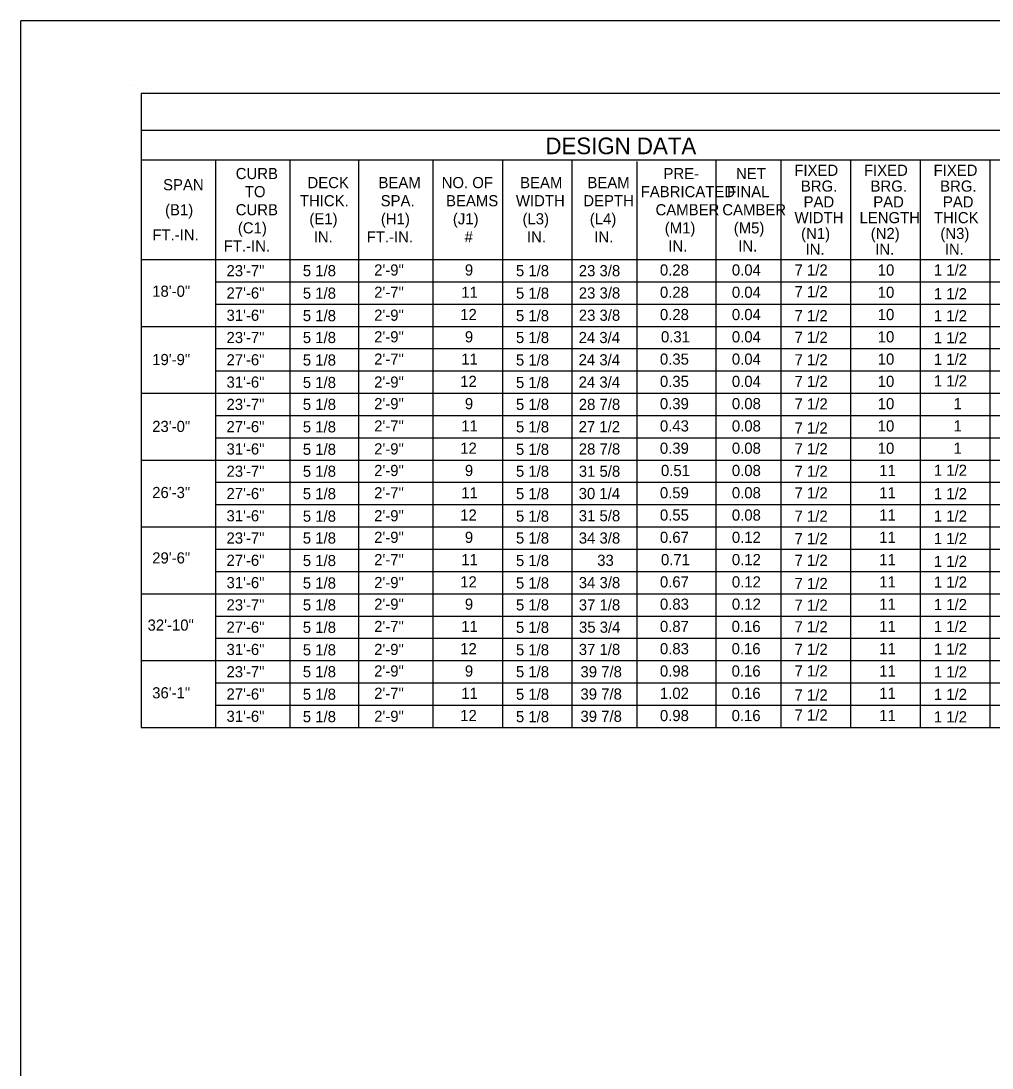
# Model space of a CAD drawing. Extents: x -5022 to -159, y 1126 to 7226.
# Drawn here: x -3800.1 to -3538.7, y 5580.8 to 5862.8 of the extents above; entities that cross this region are included whole.
import ezdxf

# ---------------------------------------------------------------- set-up
doc = ezdxf.new("R2010")
doc.units = 0
doc.layers.add('2', color=7, linetype='Continuous')
doc.layers.add('3', color=7, linetype='Continuous')

msp = doc.modelspace()

# ---------------------------------------------------------------- linework, layer by layer
at = {"layer": '2'}
for p, q in [((-3014.13, 5862.81), (-3800.13, 5862.81)), ((-3800.13, 5298.81), (-3800.13, 5862.81)), ((-3769.75, 5845.32), (-3769.75, 5845.32)), ((-3766.35, 5844.74), (-3766.35, 5844.74)), ((-3766.35, 5844.74), (-3766.35, 5844.74))]:
    msp.add_line(p, q, dxfattribs=at)
at = {"layer": '3'}
for p, q in [((-3767.78, 5843.35), (-3767.78, 5672.54)), ((-3767.78, 5843.35), (-3053.03, 5843.35)), ((-3767.78, 5833.43), (-3053.03, 5833.43)), ((-3767.78, 5825.36), (-3053.03, 5825.36)), ((-3747.78, 5825.36), (-3747.78, 5672.54)), ((-3727.78, 5825.36), (-3727.78, 5672.54)), ((-3709.28, 5825.36), (-3709.28, 5672.54)), ((-3689.28, 5825.36), (-3689.28, 5672.54)), ((-3670.53, 5825.36), (-3670.53, 5672.54)), ((-3651.78, 5825.36), (-3651.78, 5672.54)), ((-3634.28, 5824.97), (-3634.28, 5672.54)), ((-3613.03, 5825.36), (-3613.03, 5672.54)), ((-3595.53, 5825.36), (-3595.53, 5672.54)), ((-3576.78, 5825.36), (-3576.78, 5672.54)), ((-3558.03, 5825.36), (-3558.03, 5672.54)), ((-3539.28, 5825.36), (-3539.28, 5672.54)), ((-3767.78, 5798.55), (-3053.03, 5798.55)), ((-3747.78, 5792.55), (-3053.03, 5792.55)), ((-3747.78, 5786.55), (-3053.03, 5786.55)), ((-3767.78, 5780.55), (-3053.03, 5780.55)), ((-3747.78, 5774.55), (-3053.03, 5774.55)), ((-3747.78, 5768.54), (-3053.03, 5768.55)), ((-3767.78, 5762.55), (-3053.03, 5762.55)), ((-3747.78, 5756.55), (-3053.03, 5756.55)), ((-3747.78, 5750.55), (-3053.03, 5750.55)), ((-3767.78, 5744.55), (-3053.03, 5744.55)), ((-3747.78, 5738.55), (-3053.03, 5738.55)), ((-3747.78, 5732.55), (-3053.03, 5732.55)), ((-3767.78, 5726.55), (-3053.03, 5726.55)), ((-3747.78, 5720.55), (-3053.03, 5720.55)), ((-3747.78, 5714.55), (-3053.03, 5714.55)), ((-3767.78, 5708.54), (-3053.03, 5708.55)), ((-3747.78, 5702.54), (-3053.03, 5702.55)), ((-3747.78, 5696.54), (-3053.03, 5696.55)), ((-3767.78, 5690.54), (-3053.03, 5690.54)), ((-3747.78, 5684.54), (-3053.03, 5684.55)), ((-3747.78, 5678.54), (-3053.03, 5678.55)), ((-3767.78, 5672.54), (-3053.03, 5672.55))]:
    msp.add_line(p, q, dxfattribs=at)

# ---------------------------------------------------------------- texts
at = {"layer": '2'}
for s, height, p in [('DESIGN DATA', 4.4793, (-3658.93, 5826.92)), ('FIXED', 3, (-3591.93, 5821.08)), ('FIXED', 3, (-3573.18, 5821.08)), ('FIXED', 3, (-3554.43, 5821.08)), ('CURB', 3, (-3742.31, 5820.21)), ('DECK', 3, (-3722.99, 5817.77)), ('BEAM', 3, (-3703.87, 5817.77)), ('NO. OF', 3, (-3686.87, 5817.77)), ('BEAM', 3, (-3665.74, 5817.77)), ('BEAM', 3, (-3647.62, 5817.77)), ('PRE-', 3, (-3627.14, 5820.21)), ('NET', 3, (-3607.61, 5820.21)), ('SPAN', 3, (-3761.86, 5817.2)), ('TO', 3, (-3739.85, 5815.33)), ('FABRICATED', 3, (-3633.28, 5815.33)), ('FINAL', 3, (-3609.99, 5815.33)), ('BRG.', 3, (-3590.16, 5816.83)), ('BRG.', 3, (-3571.41, 5816.83)), ('BRG.', 3, (-3552.66, 5816.83)), ('THICK.', 3, (-3725.04, 5812.89)), ('SPA.', 3, (-3703.29, 5812.89)), ('BEAMS', 3, (-3685.68, 5812.89)), ('WIDTH', 3, (-3666.87, 5812.89)), ('DEPTH', 3, (-3648.74, 5812.89)), ('PAD', 3, (-3589.43, 5812.58)), ('PAD', 3, (-3570.68, 5812.58)), ('PAD', 3, (-3551.93, 5812.58)), ('(B1)', 3, (-3761.33, 5810.46)), ('CURB', 3, (-3742.31, 5810.46)), ('CAMBER', 3, (-3629.28, 5810.46)), ('CAMBER', 3, (-3611.31, 5810.46)), ('(E1)', 3, (-3722.48, 5808.02)), ('(H1)', 3, (-3703.23, 5808.02)), ('(J1)', 3, (-3683.85, 5808.02)), ('(L3)', 3, (-3665.1, 5808.02)), ('(L4)', 3, (-3646.98, 5808.02)), ('WIDTH', 3, (-3591.86, 5808.33)), ('LENGTH', 3, (-3574.36, 5808.33)), ('THICK', 3, (-3554.36, 5808.33)), ('FT.-IN.', 3, (-3764.76, 5803.7)), ('(C1)', 3, (-3741.73, 5805.58)), ('(M1)', 3, (-3626.81, 5805.58)), ('(M5)', 3, (-3608.23, 5805.58)), ('(N1)', 3, (-3590.1, 5804.08)), ('(N2)', 3, (-3571.35, 5804.08)), ('(N3)', 3, (-3552.6, 5804.08)), ('FT.-IN.', 3, (-3745.53, 5800.71)), ('IN.', 3, (-3721.29, 5803.14)), ('FT.-IN.', 3, (-3707.04, 5803.14)), ('#', 3, (-3680.7, 5803.14)), ('IN.', 3, (-3663.91, 5803.14)), ('IN.', 3, (-3645.79, 5803.14)), ('IN.', 3, (-3625.86, 5800.71)), ('IN.', 3, (-3607.03, 5800.71)), ('IN.', 3, (-3588.91, 5799.83)), ('IN.', 3, (-3570.16, 5799.83)), ('IN.', 3, (-3551.41, 5799.83)), ('23\'-7"', 3, (-3744.79, 5794.05)), ('5 1/8', 3, (-3724.24, 5794.05)), ('2\'-9"', 3, (-3705.04, 5794.24)), ('9', 3, (-3680.62, 5794.24)), ('5 1/8', 3, (-3666.87, 5794.05)), ('23 3/8', 3, (-3649.95, 5794.05)), ('0.28', 3, (-3628.11, 5794.24)), ('0.04', 3, (-3608.74, 5794.24)), ('7 1/2', 3, (-3591.86, 5794.24)), ('10', 3, (-3569.47, 5794.24)), ('1 1/2', 3, (-3554.36, 5794.24)), ('18\'-0"', 3, (-3764.79, 5788.52)), ('27\'-6"', 3, (-3744.79, 5788.05)), ('5 1/8', 3, (-3724.24, 5787.99)), ('2\'-7"', 3, (-3705.04, 5788.24)), ('11', 3, (-3681.58, 5788.24)), ('5 1/8', 3, (-3666.87, 5787.99)), ('23 3/8', 3, (-3649.95, 5788.05)), ('0.28', 3, (-3628.11, 5788.24)), ('0.04', 3, (-3608.74, 5788.24)), ('7 1/2', 3, (-3591.86, 5788.41)), ('10', 3, (-3569.47, 5788.24)), ('1 1/2', 3, (-3554.36, 5787.84)), ('31\'-6"', 3, (-3744.79, 5782.04)), ('5 1/8', 3, (-3724.24, 5781.94)), ('2\'-9"', 3, (-3705.04, 5782.06)), ('12', 3, (-3681.87, 5782.24)), ('5 1/8', 3, (-3666.87, 5781.94)), ('23 3/8', 3, (-3649.95, 5782.05)), ('0.28', 3, (-3628.11, 5782.24)), ('0.04', 3, (-3608.74, 5782.24)), ('7 1/2', 3, (-3591.86, 5781.93)), ('10', 3, (-3569.47, 5782.24)), ('1 1/2', 3, (-3554.36, 5781.91)), ('23\'-7"', 3, (-3744.79, 5776.05)), ('5 1/8', 3, (-3724.24, 5776.05)), ('2\'-9"', 3, (-3705.04, 5776.24)), ('9', 3, (-3680.62, 5776.24)), ('5 1/8', 3, (-3666.87, 5776.05)), ('24 3/4', 3, (-3649.99, 5776.05)), ('0.31', 3, (-3627.83, 5776.24)), ('0.04', 3, (-3608.74, 5776.24)), ('7 1/2', 3, (-3591.86, 5776.1)), ('10', 3, (-3569.47, 5776.24)), ('1 1/2', 3, (-3554.36, 5775.98)), ('19\'-9"', 3, (-3764.79, 5770.12)), ('27\'-6"', 3, (-3744.79, 5770.05)), ('5 1/8', 3, (-3724.24, 5769.99)), ('2\'-7"', 3, (-3705.04, 5770.24)), ('11', 3, (-3681.58, 5770.24)), ('5 1/8', 3, (-3666.87, 5769.99)), ('24 3/4', 3, (-3649.99, 5770.05)), ('0.35', 3, (-3628.11, 5770.24)), ('0.04', 3, (-3608.74, 5770.24)), ('7 1/2', 3, (-3591.86, 5770.05)), ('10', 3, (-3569.47, 5770.24)), ('1 1/2', 3, (-3554.36, 5770.18)), ('31\'-6"', 3, (-3744.79, 5764.04)), ('5 1/8', 3, (-3724.24, 5763.94)), ('2\'-9"', 3, (-3705.04, 5764.06)), ('12', 3, (-3681.87, 5764.24)), ('5 1/8', 3, (-3666.87, 5763.94)), ('24 3/4', 3, (-3649.99, 5764.04)), ('0.35', 3, (-3628.11, 5764.24)), ('0.04', 3, (-3608.74, 5764.24)), ('7 1/2', 3, (-3591.86, 5764.22)), ('10', 3, (-3569.47, 5764.24)), ('1 1/2', 3, (-3554.36, 5764.37)), ('2\'-9"', 3, (-3705.04, 5758.24)), ('9', 3, (-3680.62, 5758.24)), ('0.39', 3, (-3628.12, 5758.24)), ('0.08', 3, (-3608.74, 5758.24)), ('7 1/2', 3, (-3591.86, 5758.17)), ('10', 3, (-3569.47, 5758.24)), ('23\'-7"', 3, (-3744.79, 5758.04)), ('5 1/8', 3, (-3724.24, 5758.04)), ('5 1/8', 3, (-3666.87, 5758.04)), ('28 7/8', 3, (-3649.95, 5758.04)), ('1', 3, (-3549.08, 5758.24)), ('23\'-0"', 3, (-3764.79, 5752.11)), ('27\'-6"', 3, (-3744.79, 5752.05)), ('5 1/8', 3, (-3724.24, 5751.99)), ('2\'-7"', 3, (-3705.04, 5752.24)), ('11', 3, (-3681.58, 5752.24)), ('5 1/8', 3, (-3666.87, 5751.99)), ('27 1/2', 3, (-3649.99, 5752.04)), ('0.43', 3, (-3628.11, 5752.24)), ('0.08', 3, (-3608.74, 5752.24)), ('7 1/2', 3, (-3591.86, 5751.69)), ('10', 3, (-3569.47, 5752.24)), ('1', 3, (-3549.08, 5752.24)), ('31\'-6"', 3, (-3744.79, 5746.04)), ('5 1/8', 3, (-3724.24, 5745.94)), ('2\'-9"', 3, (-3705.04, 5746.06)), ('12', 3, (-3681.87, 5746.24)), ('5 1/8', 3, (-3666.87, 5745.94)), ('28 7/8', 3, (-3649.95, 5746.04)), ('0.39', 3, (-3628.12, 5746.24)), ('0.08', 3, (-3608.74, 5746.24)), ('7 1/2', 3, (-3591.86, 5746.08)), ('10', 3, (-3569.47, 5746.24)), ('1', 3, (-3549.08, 5746.24)), ('23\'-7"', 3, (-3744.79, 5740.04)), ('5 1/8', 3, (-3724.24, 5740.04)), ('2\'-9"', 3, (-3705.04, 5740.24)), ('9', 3, (-3680.62, 5740.24)), ('5 1/8', 3, (-3666.87, 5740.04)), ('31 5/8', 3, (-3649.95, 5740.04)), ('0.51', 3, (-3627.83, 5740.24)), ('0.08', 3, (-3608.74, 5740.24)), ('7 1/2', 3, (-3591.86, 5740.03)), ('11', 3, (-3569.08, 5740.24)), ('1 1/2', 3, (-3554.36, 5740.3)), ('26\'-3"', 3, (-3764.79, 5734.31)), ('27\'-6"', 3, (-3744.79, 5734.04)), ('5 1/8', 3, (-3724.24, 5733.99)), ('2\'-7"', 3, (-3705.04, 5734.24)), ('11', 3, (-3681.58, 5734.24)), ('5 1/8', 3, (-3666.87, 5733.99)), ('30 1/4', 3, (-3649.99, 5734.04)), ('0.59', 3, (-3628.12, 5734.24)), ('0.08', 3, (-3608.74, 5734.24)), ('7 1/2', 3, (-3591.86, 5734.2)), ('11', 3, (-3569.08, 5734.24)), ('1 1/2', 3, (-3554.36, 5734.01)), ('31\'-6"', 3, (-3744.79, 5728.04)), ('5 1/8', 3, (-3724.24, 5727.94)), ('2\'-9"', 3, (-3705.04, 5728.06)), ('12', 3, (-3681.87, 5728.24)), ('5 1/8', 3, (-3666.87, 5727.94)), ('31 5/8', 3, (-3649.95, 5728.05)), ('0.55', 3, (-3628.11, 5728.24)), ('0.08', 3, (-3608.74, 5728.24)), ('7 1/2', 3, (-3591.86, 5727.94)), ('11', 3, (-3569.08, 5728.24)), ('1 1/2', 3, (-3554.36, 5727.96)), ('23\'-7"', 3, (-3744.79, 5722.05)), ('5 1/8', 3, (-3724.24, 5722.05)), ('2\'-9"', 3, (-3705.04, 5722.24)), ('9', 3, (-3680.62, 5722.24)), ('5 1/8', 3, (-3666.87, 5722.05)), ('34 3/8', 3, (-3649.95, 5722.05)), ('0.67', 3, (-3628.11, 5722.24)), ('0.12', 3, (-3608.74, 5722.24)), ('7 1/2', 3, (-3591.86, 5721.89)), ('11', 3, (-3569.08, 5722.24)), ('1 1/2', 3, (-3554.36, 5721.92)), ('29\'-6"', 3, (-3764.79, 5716.7)), ('27\'-6"', 3, (-3744.79, 5716.05)), ('5 1/8', 3, (-3724.24, 5715.99)), ('2\'-7"', 3, (-3705.04, 5716.24)), ('11', 3, (-3681.58, 5716.24)), ('5 1/8', 3, (-3666.87, 5715.99)), ('33', 3, (-3644.99, 5716.05)), ('0.71', 3, (-3627.83, 5716.24)), ('0.12', 3, (-3608.74, 5716.24)), ('7 1/2', 3, (-3591.86, 5716.06)), ('11', 3, (-3569.08, 5716.24)), ('1 1/2', 3, (-3554.36, 5715.75)), ('1 1/2', 3, (-3554.36, 5710.18)), ('31\'-6"', 3, (-3744.79, 5710.04)), ('5 1/8', 3, (-3724.24, 5709.94)), ('2\'-9"', 3, (-3705.04, 5710.06)), ('12', 3, (-3681.87, 5710.24)), ('5 1/8', 3, (-3666.87, 5709.94)), ('34 3/8', 3, (-3649.95, 5710.04)), ('0.67', 3, (-3628.11, 5710.24)), ('0.12', 3, (-3608.74, 5710.24)), ('7 1/2', 3, (-3591.86, 5709.8)), ('11', 3, (-3569.08, 5710.24)), ('23\'-7"', 3, (-3744.79, 5704.04)), ('5 1/8', 3, (-3724.24, 5704.04)), ('2\'-9"', 3, (-3705.04, 5704.24)), ('9', 3, (-3680.62, 5704.24)), ('5 1/8', 3, (-3666.87, 5704.04)), ('37 1/8', 3, (-3649.95, 5704.04)), ('0.83', 3, (-3628.11, 5704.24)), ('0.12', 3, (-3608.74, 5704.24)), ('7 1/2', 3, (-3591.86, 5703.97)), ('11', 3, (-3569.08, 5704.24)), ('1 1/2', 3, (-3554.36, 5704.13)), ('32\'-10"', 3, (-3766.04, 5698.61)), ('27\'-6"', 3, (-3744.79, 5698.04)), ('5 1/8', 3, (-3724.24, 5697.99)), ('2\'-7"', 3, (-3705.04, 5698.24)), ('11', 3, (-3681.58, 5698.24)), ('5 1/8', 3, (-3666.87, 5697.99)), ('35 3/4', 3, (-3649.9, 5698.04)), ('0.87', 3, (-3628.11, 5698.24)), ('0.16', 3, (-3608.81, 5698.24)), ('7 1/2', 3, (-3591.86, 5698.14)), ('11', 3, (-3569.08, 5698.24)), ('1 1/2', 3, (-3554.36, 5698.2)), ('31\'-6"', 3, (-3744.79, 5692.04)), ('5 1/8', 3, (-3724.24, 5691.94)), ('2\'-9"', 3, (-3705.04, 5692.05)), ('12', 3, (-3681.87, 5692.24)), ('5 1/8', 3, (-3666.87, 5691.94)), ('37 1/8', 3, (-3649.95, 5692.04)), ('0.83', 3, (-3628.11, 5692.24)), ('0.16', 3, (-3608.81, 5692.24)), ('7 1/2', 3, (-3591.86, 5692.09)), ('11', 3, (-3569.08, 5692.24)), ('1 1/2', 3, (-3554.36, 5692.16)), ('23\'-7"', 3, (-3744.79, 5686.04)), ('5 1/8', 3, (-3724.24, 5686.04)), ('2\'-9"', 3, (-3705.04, 5686.24)), ('9', 3, (-3680.62, 5686.24)), ('5 1/8', 3, (-3666.87, 5686.04)), ('39 7/8', 3, (-3649.5, 5686.04)), ('0.98', 3, (-3628.11, 5686.24)), ('0.16', 3, (-3608.81, 5686.24)), ('7 1/2', 3, (-3591.86, 5686.26)), ('11', 3, (-3569.08, 5686.24)), ('1 1/2', 3, (-3554.36, 5685.99)), ('36\'-1"', 3, (-3764.79, 5680.37)), ('27\'-6"', 3, (-3744.79, 5680.04)), ('5 1/8', 3, (-3724.24, 5679.99)), ('2\'-7"', 3, (-3705.04, 5680.24)), ('11', 3, (-3681.58, 5680.24)), ('5 1/8', 3, (-3666.87, 5679.99)), ('39 7/8', 3, (-3649.5, 5680.04)), ('1.02', 3, (-3628.11, 5680.24)), ('0.16', 3, (-3608.81, 5680.24)), ('7 1/2', 3, (-3591.86, 5679.78)), ('11', 3, (-3569.08, 5680.24)), ('1 1/2', 3, (-3554.36, 5679.94)), ('31\'-6"', 3, (-3744.79, 5674.04)), ('5 1/8', 3, (-3724.24, 5673.94)), ('2\'-9"', 3, (-3705.04, 5674.05)), ('12', 3, (-3681.87, 5674.24)), ('5 1/8', 3, (-3666.87, 5673.94)), ('39 7/8', 3, (-3649.5, 5674.04)), ('0.98', 3, (-3628.11, 5674.24)), ('0.16', 3, (-3608.81, 5674.24)), ('7 1/2', 3, (-3591.86, 5674.38)), ('11', 3, (-3569.08, 5674.24)), ('1 1/2', 3, (-3554.36, 5673.9))]:
    msp.add_text(s, height=height, dxfattribs=at).set_placement(p)

doc.saveas('drawing.dxf')
